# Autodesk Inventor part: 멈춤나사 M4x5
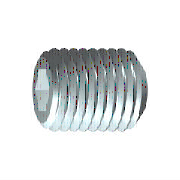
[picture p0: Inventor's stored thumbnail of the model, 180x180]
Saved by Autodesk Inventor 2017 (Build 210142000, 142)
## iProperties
IsCustomPart: 1
Created: 2012-02
Part Number: 멈춤나사 M4x5
Material: 강철, 연강
Description: 6각 소켓 머리 없는 멈춤 나사
Document SubType Name: Modeling
Standard: KS B 1028
Designer: mduedu
Standards Organization: KS
Language: ko-KR
Size Designation: 납작점M4x5
Categories: <MemberInstance><Categories><Category DisplayName="조임쇠" InternalName="e4da775c-781d-43d5-af7c-5136215cf5a6" Mnemonic="FSTN"><Category DisplayName="볼트" InternalN
Density: 1 g/cm^3
Appearance: 강철
Author: mduedu
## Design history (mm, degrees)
sketch "스케치1"
  geometry: L1 (0, 0)-(1.833, 0); L2 (5, 1.155)-(5, 2); L3 (5, 2)-(0, 2); L4 (5, 1.155)-(2.5, 1.155); L5 (2.5, 1.155)-(1.833, 0); L6 (0, -0.4)-(0, 2.4) reference; L7 (0, 2)-(0, 0)
  constraints: 13 end point, 3 parallel, 1 collinear, 1 perpendicular, 1 point on line
  dimensions: "d0" = 2.5 distance of L2.start L4.end (= INTI); "d1" = 60 deg angle of L5 L1; "d2" = 4 diameter of L3 L1 (= NND); "d3" = 2.3094 diameter of L4 L1 (= 1.1547 x SW); "d5" = 5 distance from line of L2 L3.end (= NLG)
revolve "본체" sketch "스케치1" stored, may be unused: angle "d6" = 90 deg
sketch "스케치2"
  geometry: L1 (-0.577, 1)-(0.577, 1); L2 (0.577, 1)-(1.155, 0); L3 (1.155, 0)-(0.577, -1); L4 (0.577, -1)-(-0.577, -1); L5 (-0.577, -1)-(-1.155, 0); L6 (-1.155, 0)-(-0.577, 1); A1 r 1.155 centre (0, 0) between (-0.577, 1) and (0.577, 1) reference; 2 further points
  constraints: 12 end point, 2 point on circle, 1 coincident, 1 horizontal, 11 other
extrude "슬롯" join sketch "스케치2" taper "d9" = 0 deg; stored distance "d21" = 10
workaxis "Work Axis1"
workplane "Work Plane1"
body "Solid1"
chamfer "모따기1" distance "d7" = 0.42941 (= -0.5 x GD1 + 0.5 x NND); stored, may be unused: angle "d8" = 45 deg (= FAWI), second distance "d29" = 0.42941 (= -0.5 x GD1 + 0.5 x NND)
feature "스레드" dims "d11" = 5 (= NLG), "d12" = 0
chamfer "모따기2" distance "d13" = 0.42941 (= -0.5 x GD1 + 0.5 x NND); stored, may be unused: angle "d14" = 45 deg (= FAWI), second distance "d30" = 0.42941 (= -0.5 x GD1 + 0.5 x NND)
other parameters: "NND" = 4 [user parameter; used in 5 equation terms], "NLG" = 5 [user parameter; used in 2 equation terms], "INTI" = 2.5 [user parameter; used in 1 equation term], "FAWI" = 45 deg [user parameter; used in 2 equation terms], "SW" = 2 [user parameter; used in 2 equation terms], "GD1" = 3.14117 (= THREADDIA - 1.2269 x PTC) [user parameter; used in 4 equation terms], "d4" = 0, "FAWI1" = 45 deg [user parameter], "d15" = 0, "d31" = 0, "GUL" = 0.42941 (= 0.61345 x PTC) [user parameter], "SPD" = 2.5 [user parameter], "TPU" = 14.28571 (computed from PTC) [user parameter], "TOA" = 30 deg [user parameter], "THREADDIA" = 4 [user parameter; used in 1 equation term], "PTC" = 0.7 [user parameter; used in 4 equation terms], "GAL" = 0.42941 (= 0.61345 x PTC) [user parameter], "E0" = 2.31 (= 1.155 x SW) [user parameter]
